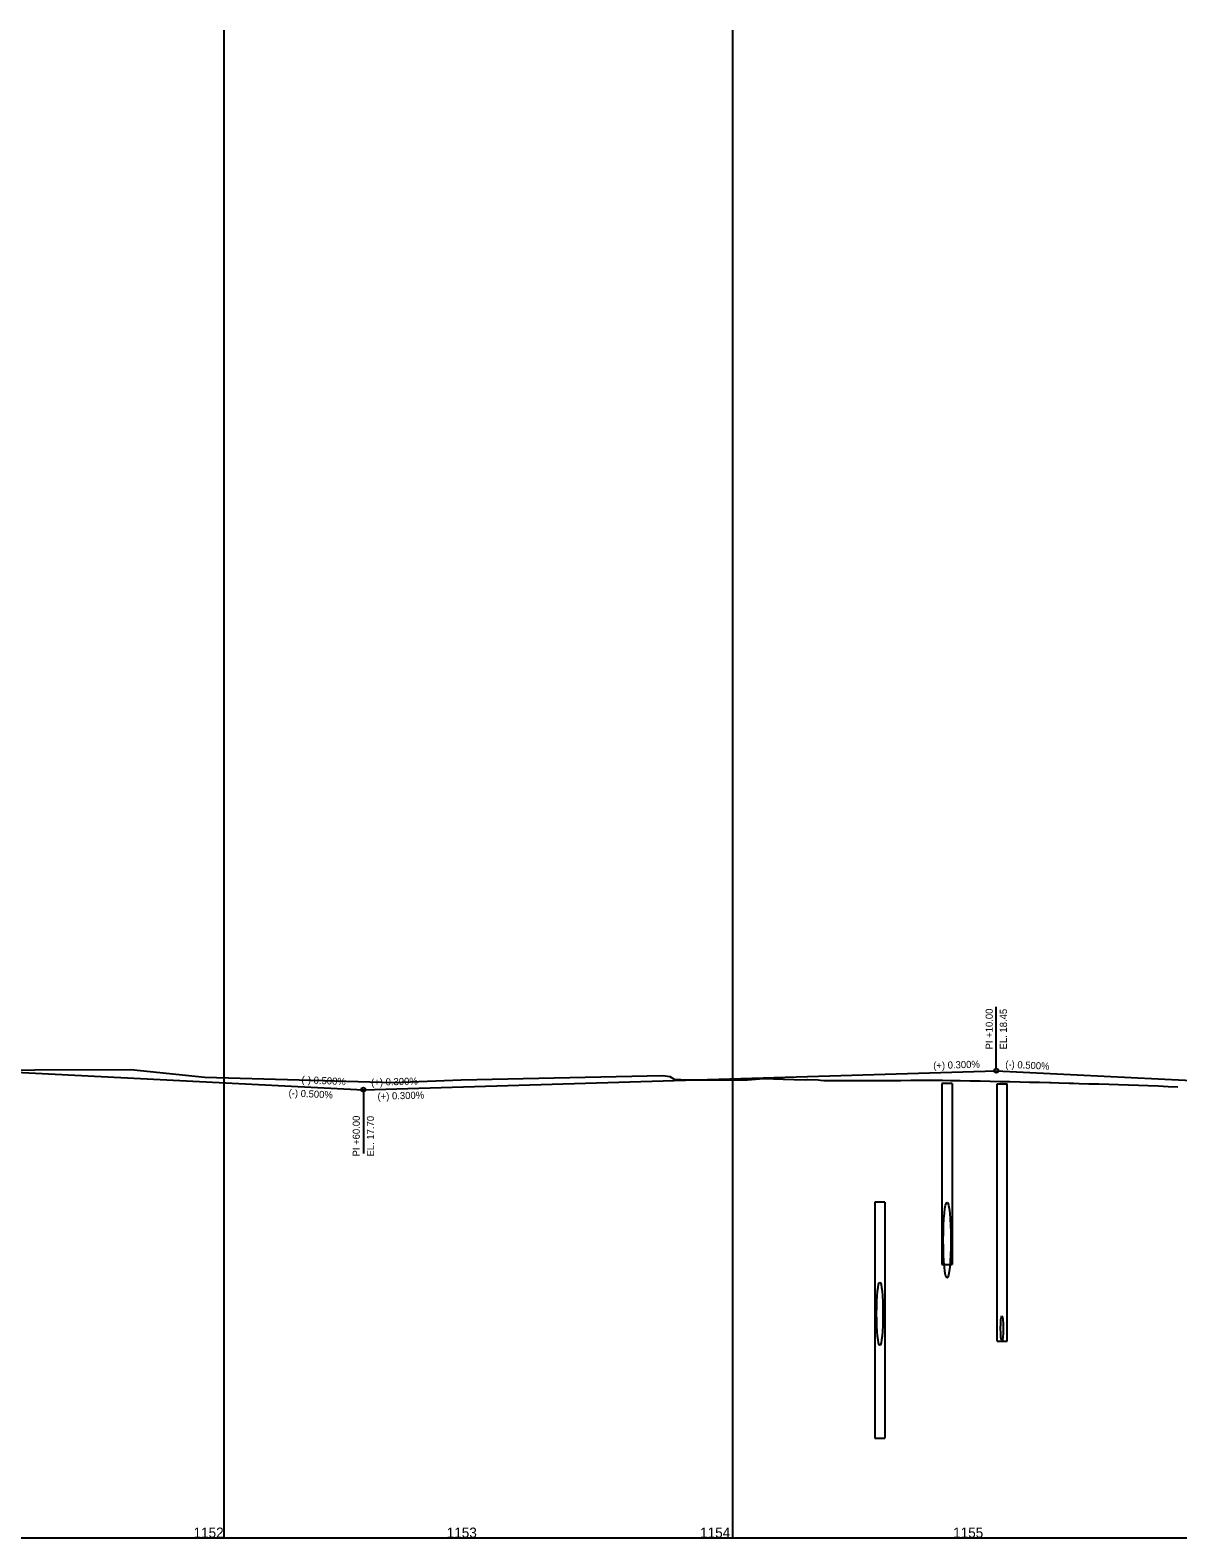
# Model space of a CAD drawing. Extents: x 1409 to 6106, y -2180 to -1584.
# Drawn here: x 4939 to 5392, y -2180 to -1584 of the extents above; entities that cross this region are included whole.
import ezdxf

# ---------------------------------------------------------------- set-up
doc = ezdxf.new("R2010")
doc.units = 0
for name, color, linetype in [('CLConst_dp', 7, 'Continuous'), ('DrainStruct_ex', 7, 'Continuous'), ('DrainStruct_pr', 7, 'Continuous'), ('LaneLine', 7, 'Continuous'), ('NonPlottingEle_dp', 7, 'Continuous'), ('PipeCulvert_ep', 7, 'Continuous'), ('PipeCulvert_pr', 7, 'Continuous'), ('StationTicS_dp', 7, 'Continuous'), ('TextLabel', 7, 'Continuous'), ('TextProfLabel', 7, 'Continuous'), ('TextPtLabel', 7, 'Continuous')]:
    doc.layers.add(name, color=color, linetype=linetype)

msp = doc.modelspace()

# ---------------------------------------------------------------- linework, layer by layer
at = {"layer": 'CLConst_dp'}
msp.add_line((1410.73, -2179.71), (6032.47, -2179.71), dxfattribs=at)
at = {"layer": 'DrainStruct_ex'}
for p, q in [((5299.27, -2036.61), (5299.27, -2071.81)), ((5303.27, -2036.61), (5303.27, -2071.81)), ((5321.04, -2102.01), (5321.04, -2035.41)), ((5325.04, -2102.01), (5325.04, -2035.41)), ((5299.27, -2071.81), (5303.27, -2071.81)), ((5321.04, -2102.01), (5325.04, -2102.01))]:
    msp.add_line(p, q, dxfattribs=at)
at = {"layer": 'DrainStruct_pr'}
for p, q in [((5299.27, -2000.21), (5299.27, -2036.61)), ((5303.27, -2000.21), (5303.27, -2036.61)), ((5321.04, -2035.41), (5321.04, -2000.41)), ((5321.04, -2000.41), (5325.04, -2000.41)), ((5325.04, -2035.41), (5325.04, -2000.41)), ((5272.72, -2047.21), (5272.72, -2140.41)), ((5276.72, -2047.21), (5276.72, -2140.41))]:
    msp.add_line(p, q, dxfattribs=at)
at = {"layer": 'NonPlottingEle_dp'}
for p, q in [((5320.73, -1994.41), (5320.73, -1970.01)), ((5070.73, -2003.51), (5070.73, -2027.91))]:
    msp.add_line(p, q, dxfattribs=at)
for centre in [(5320.73, -1995.21), (5070.73, -2002.71)]:
    msp.add_circle(centre, 0.8, dxfattribs=at)
at = {"layer": 'PipeCulvert_ep'}
for centre, major_axis in [((5301.31, -2062.11), (0, 15)), ((5274.73, -2091.21), (0, 12.5)), ((5322.93, -2097.01), (0, 5))]:
    msp.add_ellipse(centre, major_axis=major_axis, ratio=0.1, dxfattribs=at)
at = {"layer": 'PipeCulvert_pr'}
for p, q in [((5303.27, -2000.21), (5299.27, -2000.21)), ((5276.72, -2047.21), (5272.72, -2047.21)), ((5272.72, -2140.41), (5276.72, -2140.41))]:
    msp.add_line(p, q, dxfattribs=at)
at = {"layer": 'StationTicS_dp'}
msp.add_lwpolyline([(4902.9, -1994.94), (4978.9, -1994.71), (5008.08, -1997.77), (5082.69, -1999.94), (5109.31, -1998.89), (5189.04, -1997.16), (5191.82, -1997.46), (5193.46, -1998.53), (5198.85, -1998.89), (5222.47, -1998.87), (5228.83, -1998.31), (5236.49, -1998.5), (5245.21, -1998.87), (5246.15, -1998.74), (5250.33, -1998.81), (5251.32, -1998.91), (5252.57, -1999.13), (5279.18, -1999.04), (5283.09, -1999.03), (5286.99, -1999.02), (5290.9, -1999.01), (5294.81, -1999.01), (5298.71, -1999.01), (5299.14, -1999.01), (5299.5, -1999.01), (5302.62, -1999.07), (5306.53, -1999.14), (5310.43, -1999.21), (5314.34, -1999.28), (5318.25, -1999.36), (5322.16, -1999.44), (5326.06, -1999.52), (5329.97, -1999.6), (5333.88, -1999.69), (5337.78, -1999.78), (5341.69, -1999.87), (5342.39, -1999.88), (5345.6, -1999.98), (5349.5, -2000.1), (5351.25, -2000.16), (5353.41, -2000.22), (5357.32, -2000.34), (5361.22, -2000.47), (5365.13, -2000.6), (5369.04, -2000.72), (5372.94, -2000.86), (5376.85, -2000.99), (5380.76, -2001.12), (5384.66, -2001.26), (5388.57, -2001.4), (5392.48, -2001.54)], dxfattribs=at)
msp.add_lwpolyline([(4902.9, -1994.94), (4978.9, -1994.71), (5008.08, -1997.77), (5082.69, -1999.94), (5109.31, -1998.89), (5189.04, -1997.16), (5191.82, -1997.46), (5193.46, -1998.53), (5198.85, -1998.89), (5222.47, -1998.87), (5228.83, -1998.31), (5236.49, -1998.5), (5245.21, -1998.87), (5246.15, -1998.74), (5250.33, -1998.81), (5251.32, -1998.91), (5252.57, -1999.13), (5279.18, -1999.04), (5283.09, -1999.03), (5286.99, -1999.02), (5290.9, -1999.01), (5294.81, -1999.01), (5298.71, -1999.01), (5299.14, -1999.01), (5299.5, -1999.01), (5302.62, -1999.07), (5306.53, -1999.14), (5310.43, -1999.21), (5314.34, -1999.28), (5318.25, -1999.36), (5322.16, -1999.44), (5326.06, -1999.52), (5329.97, -1999.6), (5333.88, -1999.69), (5337.78, -1999.78), (5341.69, -1999.87), (5342.39, -1999.88), (5345.6, -1999.98), (5349.5, -2000.1), (5351.25, -2000.16), (5353.41, -2000.22), (5357.32, -2000.34), (5361.22, -2000.47), (5365.13, -2000.6), (5369.04, -2000.72), (5372.94, -2000.86), (5376.85, -2000.99), (5380.76, -2001.12), (5384.66, -2001.26), (5388.57, -2001.4), (5392.48, -2001.54)], dxfattribs=at)
at = {"layer": 'TextLabel'}
for p, q in [((5015.73, -2179.71), (5015.73, -1584.14)), ((5216.73, -2179.71), (5216.73, -1584.14))]:
    msp.add_line(p, q, dxfattribs=at)
at = {"layer": 'TextPtLabel'}
for p, q in [((4810.73, -1989.71), (5070.73, -2002.71)), ((5070.73, -2002.71), (5320.73, -1995.21)), ((5320.73, -1995.21), (5904.73, -2024.41))]:
    msp.add_line(p, q, dxfattribs=at)

# ---------------------------------------------------------------- texts
at = {"layer": 'LaneLine'}
for s, rotation, p in [('(+) 0.300%', 1.71836, (5295.86, -1994.56)), ('(-) 0.500%', 357.13759, (5324.23, -1993.99)), ('(-) 0.500%', 357.13759, (5046.26, -2000.09)), ('(+) 0.300%', 1.71836, (5073.85, -2001.22)), ('(-) 0.500%', 357.13759, (5041.15, -2005.34)), ('(+) 0.300%', 1.71836, (5076.37, -2006.75))]:
    msp.add_text(s, height=2.8, rotation=rotation, dxfattribs=at).set_placement(p)
at = {"layer": 'NonPlottingEle_dp'}
for s, p in [('PI +10.00', (5319.33, -1986.81)), ('EL. 18.45', (5324.93, -1986.81)), ('PI +60.00', (5069.33, -2029.11)), ('EL. 17.70', (5074.93, -2029.11))]:
    msp.add_text(s, height=2.8, rotation=90, dxfattribs=at).set_placement(p)
at = {"layer": 'TextProfLabel'}
for s, p in [('1152', (5003.66, -2179.71)), ('1153', (5103.66, -2179.71)), ('1154', (5203.74, -2179.71)), ('1155', (5303.68, -2179.71))]:
    msp.add_text(s, height=4, dxfattribs=at).set_placement(p)

doc.saveas('drawing.dxf')
